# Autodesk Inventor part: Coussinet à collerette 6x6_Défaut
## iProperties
Shininess: 64.0
Length Units: 11269
Angle Units: 11279
Time Units: 11290
Mass Units: 11283
Length Display Precision: 3
Angle Display Precision: 2
Compacted: True
Part Number: Coussinet à collerette 6x6_Défaut
Document SubType Name: Modeling
Created: 2006-01
Material: Par défaut
Designer: riri
Density: 0.0
Volumn: 0.0
Area: 0.0
PropertySet Name: Model Information
Control State: 0
Master: False
Checked Out: False
Author: riri
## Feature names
1. Base1
